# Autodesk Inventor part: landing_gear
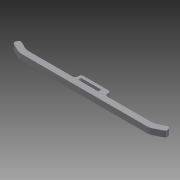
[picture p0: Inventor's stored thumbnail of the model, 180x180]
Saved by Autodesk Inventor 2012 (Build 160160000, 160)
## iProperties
Created: 2011-06
Part Number: landing_gear
Document SubType Name: Modeling
Designer: Bruce
Density: 1 g/cm^3
Material: Default
Author: Bruce
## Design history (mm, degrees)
sketch "Sketch1"
  geometry: L1 (0, 0)-(0, 30.066); L2 (-130, 0)-(-130, 30.066); L3 (-130, 0)-(0, 0); L4 (0, 5)-(-130, 5); L5 (-120, 0)-(-120, 33.471); L6 (-10, 0)-(-10, 30.983); L7 (-120, 0)-(-10, 0); L8 (-120, 0)-(-130, 5); L9 (-10, 0)-(0, 5); L10 (-118.82, 5)-(-127.764, 9.472); L11 (-11.18, 5)-(-2.236, 9.472); L12 (-118.82, 5)-(-11.18, 5); L13 (-2.236, 9.472)-(0, 5); L14 (-130, 5)-(-127.764, 9.472); L15 (-77.5, 5)-(-77.5, 10); L16 (-77.5, 10)-(-52.5, 10); L17 (-52.5, 10)-(-52.5, 5); L18 (-75, 5)-(-75, 7.5); L19 (-75, 7.5)-(-55, 7.5); L20 (-55, 7.5)-(-55, 5)
  constraints: 40 end point, 10 perpendicular, 8 point on line, 6 parallel, 1 collinear, 1 vertical
  dimensions: "d0" = 130 distance between parallel lines of L1 L2 (= hub_width); "d1" = 5 distance between parallel lines of L3 L4 (= gear_height); "d2" = 10 distance between parallel lines of L5 L2 (= gear_bend_distance); "d3" = 10 distance between parallel lines of L1 L6 (= gear_bend_distance); "d4" = 5 distance between parallel lines of L10 L8 (= gear_thickness); "d5" = 5 distance between parallel lines of L7 L12 (= gear_thickness); "d6" = 5 distance between parallel lines of L9 L11 (= gear_thickness); "d7" = 5 distance between parallel lines of L4 L16 (= 2 x structural_cover); "d8" = 25 distance between parallel lines of L17 L15 (= battery_mount_width + 2 x structural_cover); "d9" = 52.5 distance between parallel lines of L2 L15 (= -0.5 x battery_mount_width + 0.5 x hub_width - structural_cover); "d10" = 2.5 distance between parallel lines of L18 L15 (= structural_cover); "d11" = 2.5 distance between parallel lines of L19 L16 (= structural_cover); "d12" = 2.5 distance between parallel lines of L17 L20 (= structural_cover)
extrude "Extrusion1" new body sketch "Sketch1" distance "d13" = 5 (= gear_thickness); taper "d14" = 0 deg
fillet "Fillet1" dims "d15" = 2
fillet "Fillet2" dims "d16" = 10
sketch "Sketch2"
  geometry: L1 (-75, 5)-(-55, 5) reference; L2 (-55, 7.5)-(-58, 7.5); L3 (-58, 7.5)-(-58, 5); L4 (-58, 5)-(-55, 5); L5 (-55, 5)-(-55, 7.5); 1 further point
  constraints: 8 end point, 2 parallel, 1 horizontal, 1 perpendicular, 1 point on line
  dimensions: "d17" = 3 distance of L4.end L3.end
extrude "Extrusion2" join sketch "Sketch2" distance "d18" = 5 (= gear_thickness); taper "d19" = 0 deg
body "Solid1"
other parameters: "hub_width" = 130 [user parameter; used in 2 equation terms], "gear_height" = 5 [user parameter; used in 1 equation term], "gear_bend_distance" = 10 [user parameter; used in 2 equation terms], "gear_thickness" = 5 [user parameter; used in 5 equation terms], "structural_cover" = 2.5 [user parameter; used in 7 equation terms], "arm_width" = 15 [user parameter; used in 1 equation term]
